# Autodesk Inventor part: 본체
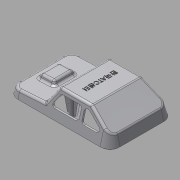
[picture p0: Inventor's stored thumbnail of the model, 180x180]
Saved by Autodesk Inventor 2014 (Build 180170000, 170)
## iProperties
Created: 2015-05
Part Number: 본체
Material: ABS 플라스틱
Document SubType Name: Modeling
Designer: Administrator
Density: 1.06 g/cm^3
Appearance: 매끄러움 - 흰색
Mass: 32.5942 g
Surface Area: 312.953 cm^2
Volume: 30.7493 cm^3
Author: Administrator
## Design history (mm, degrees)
sketch "스케치1"
  geometry: L1 (-49, 38)-(49, 38); L2 (61, 26)-(61, -26); L3 (49, -38)-(-49, -38); L4 (-61, -26)-(-61, 26); L5 (-61, 38)-(61, -38); L6 (61, 38)-(-61, -38); A1 r 12 centre (-49, 26) between (-49, 38) and (-61, 26); A2 r 12 centre (49, 26) between (61, 26) and (49, 38); A3 r 12 centre (49, -26) between (49, -38) and (61, -26); A4 r 12 centre (-49, -26) between (-61, -26) and (-49, -38); 1 further point
  constraints: 12 end point, 8 point on circle, 8 point on line, 8 tangent, 4 centre point, 3 equal radius, 2 midpoint, 2 parallel, 1 horizontal, 1 perpendicular
  dimensions: "d0" = 122 distance of L5.end L6.end; "d1" = 76 distance of L6.start L5.end; "d2" = 12 radius of A1
extrude "돌출1" new body sketch "스케치1" distance "d3" = 30; taper "d4" = -15 deg
sketch "스케치2"
  geometry: L1 (-61, 30)-(-61, 10); L2 (-61, 10)-(-31, 30); L3 (-31, 30)-(-61, 30); L4 (-61, 0)-(-52.962, 30) reference; L5 (-49, 30)-(49, 30) reference; 1 further point
  constraints: 6 end point, 1 collinear, 1 perpendicular, 1 vertical, 1 vertical alignment
  dimensions: "d5" = 20 distance of L1.start L1.end; "d6" = 30 distance of L2.end L1.start
extrude "돌출2" cut sketch "스케치2" stored distance "d7" = 30; taper "d8" = 0 deg
sketch "스케치3"
  geometry: L1 (6.628, 30)-(61, 30); L2 (61, 30)-(61, 8); L3 (19, 10.201)-(6.628, 30); L4 (-31, 30)-(49, 30) reference; L5 (61, 0)-(52.962, 30) reference; L6 (49, 0)-(61, 0) reference; L7 (19, 10.201)-(61, 8); 1 further point
  constraints: 8 end point, 1 collinear, 1 horizontal, 1 perpendicular, 1 vertical alignment
  dimensions: "d11" = 3 deg angle of L6 L7; "d12" = 8 distance from line of L6 L2.end; "d13" = 125 deg angle of L7 L3; "d14" = 42 horizontal distance of L2.end L3.start
extrude "돌출3" cut sketch "스케치3" stored distance "d15" = 30; taper "d16" = 0 deg
sketch "스케치4"
  geometry: L1 (-31.476, 48.267)-(-11.476, 48.267); L2 (-11.476, 48.267)-(-11.476, 22.267); L3 (-11.476, 22.267)-(-31.476, 22.267); L4 (-31.476, 22.267)-(-31.476, 48.267); L5 (-42.476, 9.267)-(-42.476, 61.267) reference; 3 further points
  constraints: 8 end point, 2 midpoint, 2 parallel, 1 horizontal, 1 horizontal alignment, 1 perpendicular
  dimensions: "d17" = 11 distance between parallel lines of L5 L4; "d18" = 20 distance of L2.end L3.end; "d19" = 26 distance of L1.end L2.end
extrude "돌출4" join sketch "스케치4" distance "d20" = 5; taper "d21" = -20 deg
fillet "모깎기1" dims "d22" = 3
fillet "모깎기2" dims "d23" = 3
fillet "모깎기3" dims "d24" = 3
fillet "모깎기4" dims "d25" = 3
feature "쉘1" dims "d26" = 2
node "작업 평면1"
sketch "스케치6"
  geometry: A1 r 4 centre (-21, 0) between (-17, 0) and (-25, 0); A2 r 4 centre (-10, 0) between (-6, 0) and (-14, 0); A3 r 4 centre (10, 0) between (14, 0) and (6, 0); A4 r 4 centre (21, 0) between (25, 0) and (17, 0); 3 further points
  constraints: 8 point on circle, 4 centre point, 4 horizontal alignment, 9 other
  dimensions: "d28" = 8 diameter of A1; "d29" = 8 diameter of A2; "d30" = 8 diameter of A3; "d31" = 8 diameter of A4; "d32" = 10 distance of point (0, 0) A2.centre; "d33" = 20 distance of A3.centre A2.centre; "d34" = 11 distance of A2.centre A1.centre; "d35" = 11 distance of A4.centre A3.centre
extrude "돌출5" join sketch "스케치6" stored distance "d36" = 5; taper "d37" = 0 deg
chamfer "모따기1" distance "d38" = 1; stored, may be unused: second distance "d39" = 2, angle "d40" = 45 deg
sketch "스케치7"
  geometry: L1 (58.929, 26)-(58.929, -26) reference; L2 (49, -35.929)-(-49, -35.929) reference; L3 (-58.929, -26)-(-58.929, 26) reference; L4 (-49, 35.929)-(49, 35.929) reference; L5 (49, 36.929)-(-49, 36.929); L6 (-59.929, 26)-(-59.929, -26); L7 (-49, -36.929)-(49, -36.929); L8 (59.929, -26)-(59.929, 26); A1 r 9.929 centre (49, -26) between (49, -35.929) and (58.929, -26) reference; A2 r 9.929 centre (-49, -26) between (-58.929, -26) and (-49, -35.929) reference; A3 r 9.929 centre (-49, 26) between (-49, 35.929) and (-58.929, 26) reference; A4 r 9.929 centre (49, 26) between (58.929, 26) and (49, 35.929) reference; A5 r 10.929 centre (-49, 26) between (-49, 36.929) and (-59.929, 26); A6 r 10.929 centre (-49, -26) between (-59.929, -26) and (-49, -36.929); A7 r 10.929 centre (49, -26) between (49, -36.929) and (59.929, -26); A8 r 10.929 centre (49, 26) between (59.929, 26) and (49, 36.929); 1 further point
  constraints: 8 end point, 8 point on circle, 4 centre point, 7 other
  dimensions: "d41" = 1 distance between parallel lines of L4 L5
extrude "돌출6" join sketch "스케치7" distance "d42" = 1; taper "d43" = 0 deg
sketch "스케치8"
  geometry: L1 (-50.664, 16.891)-(-31.756, 29.496) reference; L2 (-30.092, 30)-(4.965, 30) reference; L3 (7.51, 28.59)-(18.172, 11.526) reference; L4 (4.738, 23.59)-(10.362, 14.59); L5 (7.818, 10)-(-17.77, 10); L6 (-20.77, 13)-(-20.77, 22); L7 (-17.77, 25)-(2.194, 25); L8 (-43.742, 15.496)-(-30.242, 24.496); L9 (-42.078, 10)-(-26.986, 10); L10 (-23.986, 13)-(-23.986, 22); L11 (-26.986, 25)-(-28.578, 25); A1 r 3 centre (-17.77, 22) between (-17.77, 25) and (-20.77, 22); A2 r 3 centre (2.194, 22) between (4.738, 23.59) and (2.194, 25); A3 r 3 centre (7.818, 13) between (7.818, 10) and (10.362, 14.59); A4 r 3 centre (-17.77, 13) between (-20.77, 13) and (-17.77, 10); A5 r 3 centre (-26.986, 22) between (-23.986, 22) and (-26.986, 25); A6 r 3 centre (-28.578, 22) between (-28.578, 25) and (-30.242, 24.496); A7 r 3 centre (-26.986, 13) between (-26.986, 10) and (-23.986, 13); A8 r 3 centre (-42.078, 13) between (-43.742, 15.496) and (-42.078, 10); 5 further points
  constraints: 16 end point, 16 point on circle, 16 tangent, 8 centre point, 8 point on line, 6 equal radius, 6 parallel, 2 perpendicular
  dimensions: "d44" = 5 distance between parallel lines of L3 L4; "d45" = 5 distance between parallel lines of L2 L7; "d46" = 15 distance between parallel lines of L5 L7; "d47" = 34 distance of point (13.23, 10) point (-20.77, 10); "d48" = 3 radius of A1; "d49" = 5 distance between parallel lines of L2 L11; "d50" = 5 distance between parallel lines of L1 L8; "d51" = 15 distance between parallel lines of L11 L9; "d52" = 28 distance of point (-51.986, 10) point (-23.986, 10); "d53" = 3 radius of A5
extrude "돌출7" cut sketch "스케치8" stored distance "d54" = 1; taper "d55" = 0 deg
sketch "스케치9"
  geometry: C1 r 3 at (-40, 0); C2 r 3 at (0, -22); C3 r 3 at (0, 22); C4 r 3 at (40, 0); 1 further point
  constraints: 4 centre point, 2 horizontal alignment, 2 vertical alignment
  dimensions: "d56" = 6 diameter of C1; "d57" = 6 diameter of C2; "d58" = 6 diameter of C3; "d59" = 6 diameter of C4; "d60" = 40 distance of C4.centre point (0, 0); "d61" = 22 distance of point (0, 0) C2.centre; "d62" = 44 distance of C3.centre C2.centre; "d63" = 40 distance of C1.centre point (0, 0)
extrude "돌출8" join sketch "스케치9" stored distance "d64" = 1; taper "d65" = 2 deg
node "작업 평면2"
sketch "스케치10"
  geometry: L1 (-45, 1)-(-35, 1); L2 (-35, 1)-(-35, -1); L3 (-35, -1)-(-45, -1); L4 (-45, -1)-(-45, 1); L5 (-45, 1)-(-35, -1); L6 (-35, 1)-(-45, -1); L7 (-5, 23)-(5, 23); L8 (5, 23)-(5, 21); L9 (5, 21)-(-5, 21); L10 (-5, 21)-(-5, 23); L11 (-5, 23)-(5, 21); L12 (5, 23)-(-5, 21); L13 (-5, -21)-(5, -21); L14 (5, -21)-(5, -23); L15 (5, -23)-(-5, -23); L16 (-5, -23)-(-5, -21); L17 (-5, -21)-(5, -23); L18 (5, -21)-(-5, -23); L19 (35, 1)-(45, 1); L20 (45, 1)-(45, -1); L21 (45, -1)-(35, -1); L22 (35, -1)-(35, 1); L23 (35, 1)-(45, -1); L24 (45, 1)-(35, -1); C1 r 3 at (-40, 0) reference; C2 r 3 at (0, 22) reference; C3 r 3 at (40, 0) reference; C4 r 3 at (0, -22) reference; 1 further point
  constraints: 48 end point, 8 midpoint, 8 parallel, 4 horizontal, 4 perpendicular
  dimensions: "d67" = 10 distance of L2.end L3.end; "d68" = 2 distance of L1.end L2.end; "d69" = 10 distance of L8.end L9.end; "d70" = 2 distance of L7.end L8.end; "d71" = 10 distance of L14.end L15.end; "d72" = 2 distance of L13.end L14.end; "d73" = 10 distance of L20.end L21.end; "d74" = 2 distance of L19.end L20.end
extrude "돌출9" join sketch "스케치10" stored distance "d75" = 1; taper "d76" = 2.5 deg
sketch "스케치11"
  geometry: L1 (2.098, 0)-(3.233, -26.025) reference; L2 (27.189, -25.764)-(-7.868, -25.764) reference; L3 (2.098, 0)-(6.64, -25.764); L4 (6.64, -25.764)-(3.221, -25.764); L5 (2.098, 0)-(3.221, -25.764); 1 further point
  constraints: 6 end point, 3 point on line, 1 collinear
  dimensions: "d79" = 80 deg angle of L2 L3
extrude "돌출10" join sketch "스케치11" stored distance "d80" = 10; taper "d81" = 0 deg
sketch "스케치14"
  geometry: L1 (2.098, 0)-(2.551, -10.4) reference; L2 (-2.896, -10.052)-(-2.902, 2.042); L3 (2.098, 0)-(4.014, -10.835); L4 (4.014, -10.835)-(2.551, -10.4); 16 further points; 9 other entities
  constraints: 6 end point, 9 other
  dimensions: "d90" = 10 deg angle of L3 L2; "d91" = 1.46262 horizontal distance of L3.end L1.end
extrude "돌출13" join sketch "스케치14" stored distance "d92" = 10; taper "d93" = 0 deg
sketch "스케치15"
  geometry: L1 (0, 0)-(-0.429, -9.83) reference; L2 (5, 2.042)-(5.006, -10.052); L3 (0, 0)-(-1.716, -9.762); L4 (-0.429, -9.83)-(-1.716, -9.762); L5 (-0.429, -9.83)-(0, 0); 16 further points; 9 other entities
  constraints: 8 end point, 10 other
  dimensions: "d94" = 10 deg angle of L3 L2
extrude "돌출14" join sketch "스케치15" stored distance "d95" = 10; taper "d96" = 0 deg
sketch "스케치16"
  geometry: L1 (2.098, 0)-(2.788, -15.818) reference; L2 (-8.934, -23.462)-(-6.199, -21.645) reference; L3 (-7.902, 0.087)-(-8.934, -23.462) reference; L4 (-7.902, 0.087)-(-5.805, 0.087) reference; L5 (2.098, 0)-(4.606, -14.605); L6 (-7.902, 0.087)-(-12.642, -26.112); L7 (-2.902, 0.044)-(-2.99, -19.592); L8 (-6.199, -21.815)-(-12.642, -26.112); L9 (2.788, -15.818)-(4.606, -14.605); L10 (-8.941, -23.644)-(-7.902, 0.087); L11 (2.788, -15.818)-(2.098, 0); 16 further points; 10 other entities
  constraints: 14 end point, 2 collinear, 1 parallel, 1 point on line, 11 other
  dimensions: "d97" = 10 deg angle of L6 L7; "d98" = 20 deg angle of L6 L5
extrude "돌출15" join sketch "스케치16" stored distance "d99" = 10; taper "d100" = 0 deg
sketch "스케치17"
  geometry: L1 (0, 0)-(-1.095, -25.103) reference; L2 (-0.813, -25.554)-(-1.095, -25.103) reference; L3 (5, -25.932)-(5, 0.044); L4 (0, 0)-(-3.693, -20.942); L5 (-1.095, -25.103)-(-3.693, -20.942); 16 further points; 9 other entities
  constraints: 6 end point, 1 collinear, 1 vertical, 9 other
  dimensions: "d101" = 10 deg angle of L3 L4
extrude "돌출16" join sketch "스케치17" stored distance "d102" = 10; taper "d103" = 0 deg
sketch "스케치18"
  geometry: L1 (-1.095, 25.103)-(-0.813, 25.554) reference; L2 (0, 0)-(-1.095, 25.103) reference; L3 (5, -0.044)-(5, 25.932); L4 (0, 0)-(-3.693, 20.942); L5 (-1.095, 25.103)-(-3.693, 20.942); 16 further points; 9 other entities
  constraints: 6 end point, 1 collinear, 1 vertical, 9 other
  dimensions: "d104" = 10 deg angle of L3 L4
extrude "돌출17" join sketch "스케치18" stored distance "d105" = 10; taper "d106" = 0 deg
sketch "스케치19"
  geometry: C1 r 3 at (0, 0) reference; C2 r 3 at (-40, -22) reference; C3 r 3 at (0, -44) reference; C4 r 3 at (40, -22) reference; 5 further points
  constraints: 4 coincident
hole "구멍1" sketch "스케치19" at (-40, -22), (0, 0), (40, -22), (0, -44) diameter "d107" = 3.242; stored, may be unused: countersink angle "d111" = 90 deg, drill point angle "d113" = 118 deg; dims "d108" = 9, "d109" = 4, "d110" = 2, "d112" = 11
sketch "스케치20"
  geometry: L1 (61, 26)-(61, -26) reference; 2 further points
  constraints: 1 horizontal alignment, 1 other
  dimensions: "d114" = 50 distance from line of L1 point (11, 0)
feature "엠보싱1" sketch "스케치20" dims "d0" = 122, "d1" = 76, "d2" = 12, "d115" = 0.5, "d116" = 0
node "솔리드1"
mirror "대칭1"
node "투영된 루프1"
node "투영된 루프2"
node "투영된 루프3"
node "투영된 루프4"
node "투영된 루프5"
node "투영된 루프6"
node "투영된 루프7"
node "투영된 루프8"
node "투영된 루프9"
node "투영된 루프10"
node "투영된 루프11"
node "투영된 루프12"
node "투영된 루프13"
other parameters: "d27" = -63, "d66" = 2
